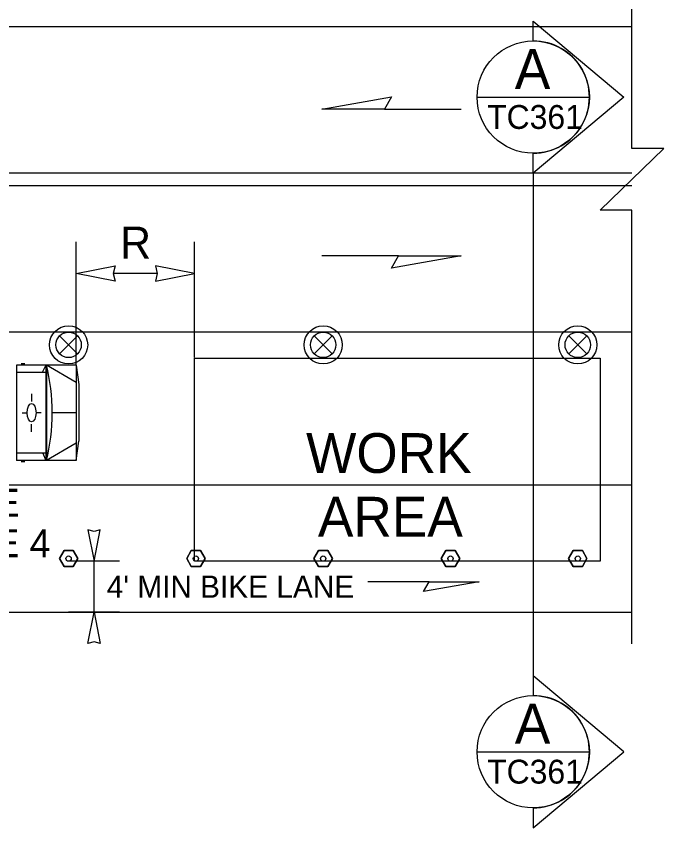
# Model space of a CAD drawing. Extents: x 99958 to 100176, y 99935 to 100011.
# Drawn here: x 100046.007 to 100047.635, y 99973.53 to 99975.571 of the extents above; entities that cross this region are included whole.
import ezdxf

# ---------------------------------------------------------------- set-up
doc = ezdxf.new("R2010")
doc.units = 0
for name, color, linetype in [('RD_ED_ShoulderPavedEdge', 7, 'Continuous'), ('RD_MK_LineDblYellowCenter', 7, 'Continuous'), ('RD_MK_LineEdgeYellow', 7, 'Continuous'), ('RD_MK_LineLane', 7, 'Continuous'), ('SH_TI_WZSectionCut', 7, 'Continuous'), ('TR_WZ_TrafficSafetyDrum', 7, 'Continuous'), ('TR_WZ_TransportableAttenuator', 7, 'Continuous'), ('TR_WZ_TubularMarker', 7, 'Continuous'), ('TR_WZ_WorkAreaLabel', 7, 'Continuous'), ('TR_WZ_WorkZoneDetails', 7, 'Continuous'), ('TR_WZ_WorkZoneTextCurrent', 7, 'Continuous')]:
    doc.layers.add(name, color=color, linetype=linetype)

msp = doc.modelspace()

# ---------------------------------------------------------------- linework, layer by layer
at = {"layer": 'RD_ED_ShoulderPavedEdge'}
msp.add_line((100044.6319, 99974.0725), (100047.555, 99974.0725), dxfattribs=at)
at = {"layer": 'RD_MK_LineDblYellowCenter'}
for p, q in [((100047.555, 99975.1765), (100044.3495, 99975.1765)), ((100047.555, 99975.1445), (100044.3495, 99975.1445))]:
    msp.add_line(p, q, dxfattribs=at)
at = {"layer": 'RD_MK_LineEdgeYellow'}
msp.add_line((100044.8819, 99974.3925), (100047.555, 99974.3925), dxfattribs=at)
at = {"layer": 'RD_MK_LineLane'}
for points in [[(100047.555, 99975.5445), (100040.32, 99975.5445)], [(100047.555, 99974.7765), (100040.32, 99974.7765)]]:
    msp.add_lwpolyline(points, dxfattribs=at)
at = {"layer": 'SH_TI_WZSectionCut'}
for p, q in [((100047.3069, 99975.5088), (100047.3069, 99975.5587)), ((100047.3069, 99975.5587), (100047.535, 99975.3676)), ((100047.535, 99975.3676), (100047.3069, 99975.1764)), ((100047.3069, 99975.1764), (100047.3069, 99975.2264)), ((100047.3069, 99975.1765), (100047.3069, 99973.9125)), ((100047.3069, 99973.9125), (100047.3069, 99973.8625)), ((100047.535, 99973.7213), (100047.3069, 99973.9125)), ((100047.3069, 99973.5302), (100047.535, 99973.7213)), ((100047.3069, 99973.5801), (100047.3069, 99973.5302))]:
    msp.add_line(p, q, dxfattribs=at)
for points in [[(100047.1656, 99975.3676), (100047.4481, 99975.3676)], [(100047.1656, 99973.7213), (100047.4481, 99973.7213)]]:
    msp.add_lwpolyline(points, dxfattribs=at)
for centre in [(100047.3069, 99975.3676), (100047.3069, 99973.7213)]:
    msp.add_circle(centre, 0.1412, dxfattribs=at)
for centre in [(100047.3069, 99975.3676), (100047.3069, 99973.7213)]:
    msp.add_arc(centre, 0.1412, 269.9978, 90.0022, dxfattribs=at)
at = {"layer": 'TR_WZ_TrafficSafetyDrum'}
for p, q in [((100046.1163, 99974.7671), (100046.1615, 99974.7218)), ((100046.1615, 99974.7671), (100046.1163, 99974.7218)), ((100046.7563, 99974.7671), (100046.8015, 99974.7218)), ((100046.8015, 99974.7671), (100046.7563, 99974.7218)), ((100047.3963, 99974.7671), (100047.4415, 99974.7218)), ((100047.4415, 99974.7671), (100047.3963, 99974.7218))]:
    msp.add_line(p, q, dxfattribs=at)
for centre, radius in [((100046.1389, 99974.7445), 0.048), ((100046.1389, 99974.7445), 0.048), ((100046.7789, 99974.7445), 0.048), ((100046.7789, 99974.7445), 0.048), ((100047.4189, 99974.7445), 0.048), ((100047.4189, 99974.7445), 0.048), ((100046.1389, 99974.7445), 0.032), ((100046.7789, 99974.7445), 0.032), ((100047.4189, 99974.7445), 0.032)]:
    msp.add_circle(centre, radius, dxfattribs=at)
at = {"layer": 'TR_WZ_TransportableAttenuator'}
for p, q in [((100046.0084, 99974.6937), (100046.0084, 99974.4537)), ((100046.1576, 99974.6937), (100046.0084, 99974.6937)), ((100046.0288, 99974.6971), (100046.0198, 99974.6971)), ((100046.0817, 99974.6937), (100046.0722, 99974.6751)), ((100046.0817, 99974.6937), (100046.0817, 99974.4537)), ((100046.083, 99974.6937), (100046.083, 99974.4537)), ((100046.1576, 99974.6497), (100046.083, 99974.6937)), ((100046.1576, 99974.6937), (100046.1576, 99974.4537)), ((100046.1576, 99974.6937), (100046.165, 99974.6452)), ((100046.0817, 99974.6751), (100046.0084, 99974.6751)), ((100046.165, 99974.6452), (100046.165, 99974.5021)), ((100046.0459, 99974.6212), (100046.0459, 99974.6018)), ((100046.022, 99974.5738), (100046.032, 99974.5738)), ((100046.0347, 99974.5732), (100046.0347, 99974.5732)), ((100046.0697, 99974.5738), (100046.0597, 99974.5738)), ((100046.1576, 99974.5737), (100046.0977, 99974.5737)), ((100046.0459, 99974.5261), (100046.0459, 99974.5455)), ((100046.1576, 99974.4976), (100046.083, 99974.4537)), ((100046.1576, 99974.4537), (100046.165, 99974.5021)), ((100046.0817, 99974.4723), (100046.0084, 99974.4723)), ((100046.0738, 99974.4723), (100046.0817, 99974.4537)), ((100046.1576, 99974.4537), (100046.0084, 99974.4537)), ((100046.0288, 99974.4503), (100046.0198, 99974.4503))]:
    msp.add_line(p, q, dxfattribs=at)
msp.add_ellipse((100045.9764, 99974.5736), major_axis=(0, 0.2519), ratio=0.481608, start_param=4.215852, end_param=5.209111, dxfattribs=at)
msp.add_ellipse((100046.0459, 99974.5737), major_axis=(0, -0.0231), ratio=0.481608, dxfattribs=at)
at = {"layer": 'TR_WZ_TubularMarker'}
for points in [[(100046.1158, 99974.2071), (100046.1274, 99974.2271), (100046.1505, 99974.2271), (100046.162, 99974.2071), (100046.1505, 99974.1871), (100046.1274, 99974.1871)], [(100046.4358, 99974.2071), (100046.4474, 99974.2271), (100046.4705, 99974.2271), (100046.482, 99974.2071), (100046.4705, 99974.1871), (100046.4474, 99974.1871)], [(100046.7558, 99974.2071), (100046.7674, 99974.2271), (100046.7905, 99974.2271), (100046.802, 99974.2071), (100046.7905, 99974.1871), (100046.7674, 99974.1871)], [(100047.0758, 99974.2071), (100047.0874, 99974.2271), (100047.1105, 99974.2271), (100047.122, 99974.2071), (100047.1105, 99974.1871), (100047.0874, 99974.1871)], [(100047.3958, 99974.2071), (100047.4074, 99974.2271), (100047.4305, 99974.2271), (100047.442, 99974.2071), (100047.4305, 99974.1871), (100047.4074, 99974.1871)]]:
    msp.add_lwpolyline(points, close=True, dxfattribs=at)
for points in [[(100046.1274, 99974.1871), (100046.1505, 99974.1871), (100046.162, 99974.2071), (100046.1505, 99974.2271), (100046.1274, 99974.2271), (100046.1158, 99974.2071), (100046.1274, 99974.1871)], [(100046.4474, 99974.1871), (100046.4705, 99974.1871), (100046.482, 99974.2071), (100046.4705, 99974.2271), (100046.4474, 99974.2271), (100046.4358, 99974.2071), (100046.4474, 99974.1871)], [(100046.7674, 99974.1871), (100046.7905, 99974.1871), (100046.802, 99974.2071), (100046.7905, 99974.2271), (100046.7674, 99974.2271), (100046.7558, 99974.2071), (100046.7674, 99974.1871)], [(100047.0874, 99974.1871), (100047.1105, 99974.1871), (100047.122, 99974.2071), (100047.1105, 99974.2271), (100047.0874, 99974.2271), (100047.0758, 99974.2071), (100047.0874, 99974.1871)], [(100047.4074, 99974.1871), (100047.4305, 99974.1871), (100047.442, 99974.2071), (100047.4305, 99974.2271), (100047.4074, 99974.2271), (100047.3958, 99974.2071), (100047.4074, 99974.1871)]]:
    msp.add_lwpolyline(points, dxfattribs=at)
for centre in [(100046.1389, 99974.2071), (100046.4589, 99974.2071), (100046.7789, 99974.2071), (100047.0989, 99974.2071), (100047.4189, 99974.2071)]:
    msp.add_circle(centre, 0.00667, dxfattribs=at)
at = {"layer": 'TR_WZ_WorkZoneDetails'}
for p, q in [((100046.9327, 99975.337), (100047.1256, 99975.337)), ((100046.1576, 99974.6937), (100046.1576, 99975.0037)), ((100046.4554, 99974.7125), (100046.4554, 99975.0037)), ((100046.9684, 99974.9685), (100046.7755, 99974.9685)), ((100046.3616, 99974.9237), (100046.2514, 99974.9237)), ((100046.2669, 99974.2005), (100046.1389, 99974.2005)), ((100046.2029, 99974.0725), (100046.2029, 99974.2005)), ((100047.0457, 99974.1488), (100046.8914, 99974.1488)), ((100046.2669, 99974.0725), (100046.1389, 99974.0725))]:
    msp.add_line(p, q, dxfattribs=at)
msp.add_lwpolyline([(100047.555, 99973.9925), (100047.555, 99975.083), (100047.475, 99975.083), (100047.635, 99975.2379), (100047.555, 99975.2379), (100047.555, 99976.3285)], dxfattribs=at)
for points in [[(100046.7755, 99975.337), (100046.9506, 99975.3679), (100046.9327, 99975.337)], [(100047.1256, 99974.9685), (100046.9506, 99974.9376), (100046.9684, 99974.9685)], [(100046.1576, 99974.9237), (100046.2559, 99974.9429), (100046.2514, 99974.9237), (100046.2559, 99974.9044)], [(100046.4554, 99974.9237), (100046.3571, 99974.9429), (100046.3616, 99974.9237), (100046.3571, 99974.9044)], [(100046.4554, 99974.2005), (100046.4554, 99974.7114), (100047.475, 99974.7114), (100047.475, 99974.2005)], [(100046.2029, 99974.2005), (100046.2183, 99974.2791), (100046.2029, 99974.2754), (100046.1875, 99974.2791)], [(100047.1714, 99974.1488), (100047.0314, 99974.1241), (100047.0457, 99974.1488)], [(100046.2029, 99974.0725), (100046.2183, 99973.9938), (100046.2029, 99973.9975), (100046.1875, 99973.9938)]]:
    msp.add_lwpolyline(points, close=True, dxfattribs=at)

# ---------------------------------------------------------------- texts
at = {"layer": 'SH_TI_WZSectionCut'}
for s, height, rotation, p in [('A', 0.1, 0.01, (100047.2606, 99975.3882)), ('TC361', 0.06, 360, (100047.191, 99975.2876)), ('A', 0.1, 0.01, (100047.2606, 99973.7419)), ('TC361', 0.06, 360, (100047.191, 99973.6413))]:
    msp.add_text(s, height=height, rotation=rotation, dxfattribs=at).set_placement(p)
at = {"layer": 'TR_WZ_WorkAreaLabel'}
for s, p in [('WORK', (100046.736, 99974.4225)), ('AREA', (100046.7657, 99974.2624))]:
    msp.add_text(s, height=0.1, dxfattribs=at).set_placement(p)
at = {"layer": 'TR_WZ_WorkZoneTextCurrent'}
for s, height, p in [('R', 0.08, (100046.2689, 99974.9617)), ('SEE', 0.07, (100045.8286, 99974.3125)), ('NOTE 4', 0.07, (100045.755, 99974.2105)), ("4' MIN BIKE LANE", 0.056, (100046.2349, 99974.1084))]:
    msp.add_text(s, height=height, dxfattribs=at).set_placement(p)

doc.saveas('drawing.dxf')
